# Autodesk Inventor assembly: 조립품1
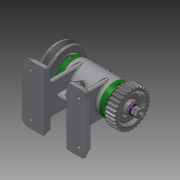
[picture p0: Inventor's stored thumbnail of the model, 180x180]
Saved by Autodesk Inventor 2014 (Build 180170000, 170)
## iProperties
Created: 2016-07
Part Number: 조립품1
Document SubType Name: Assembly
Designer: net
Author: net
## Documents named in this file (16)
- C:\Users\net\Desktop\조립품1.iam
- C:\Users\net\Desktop\부품1.ipt
- C:\Users\net\Desktop\460707V1002\축.ipt
- C:\Users\net\Desktop\460707V1002\베어링 15 x 32 x 9.ipt
- C:\Users\net\Desktop\460707V1002\키 3 x 3 x 12.ipt
- C:\Users\net\Desktop\460707V1002\커버.ipt
- C:\Users\net\Desktop\460707V1002\니플 M 6 x 0.75.ipt
- C:\Users\net\Desktop\460707V1002\볼트 M 6 x 8.ipt
- C:\Users\net\Desktop\460707V1002\볼트 M4 x 12.ipt
- C:\Users\net\Desktop\460707V1002\오일 실 15 25 7.ipt
- C:\Users\net\Desktop\460707V1002\V벨트풀리.ipt
- C:\Users\net\Desktop\460707V1002\스퍼기어.ipt
- C:\Users\net\Desktop\460707V1002\와셔 6x11.5.ipt
- C:\Users\net\Desktop\460707V1002\스프링와셔 8.ipt
- C:\Users\net\Desktop\460707V1002\너트 M 8.ipt
- C:\Users\net\Desktop\460707V1002\와셔 8x17.ipt
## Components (11 placed, 3 different names)
1. KS B 2023 6002 - 15 x 32 x 9:1
2. KS B 2023 6002 - 15 x 32 x 9:2
3. V벨트풀리:1
4. ISO 4762 M4 x 12:2
5. ISO 4762 M4 x 12:3
6. ISO 4762 M4 x 12:4
7. ISO 4762 M4 x 12:5
8. ISO 4762 M4 x 12:1
9. ISO 4762 M4 x 12:6
10. ISO 4762 M4 x 12:7
11. ISO 4762 M4 x 12:8
